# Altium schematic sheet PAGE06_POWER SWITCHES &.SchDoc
size 391 x 287 mm
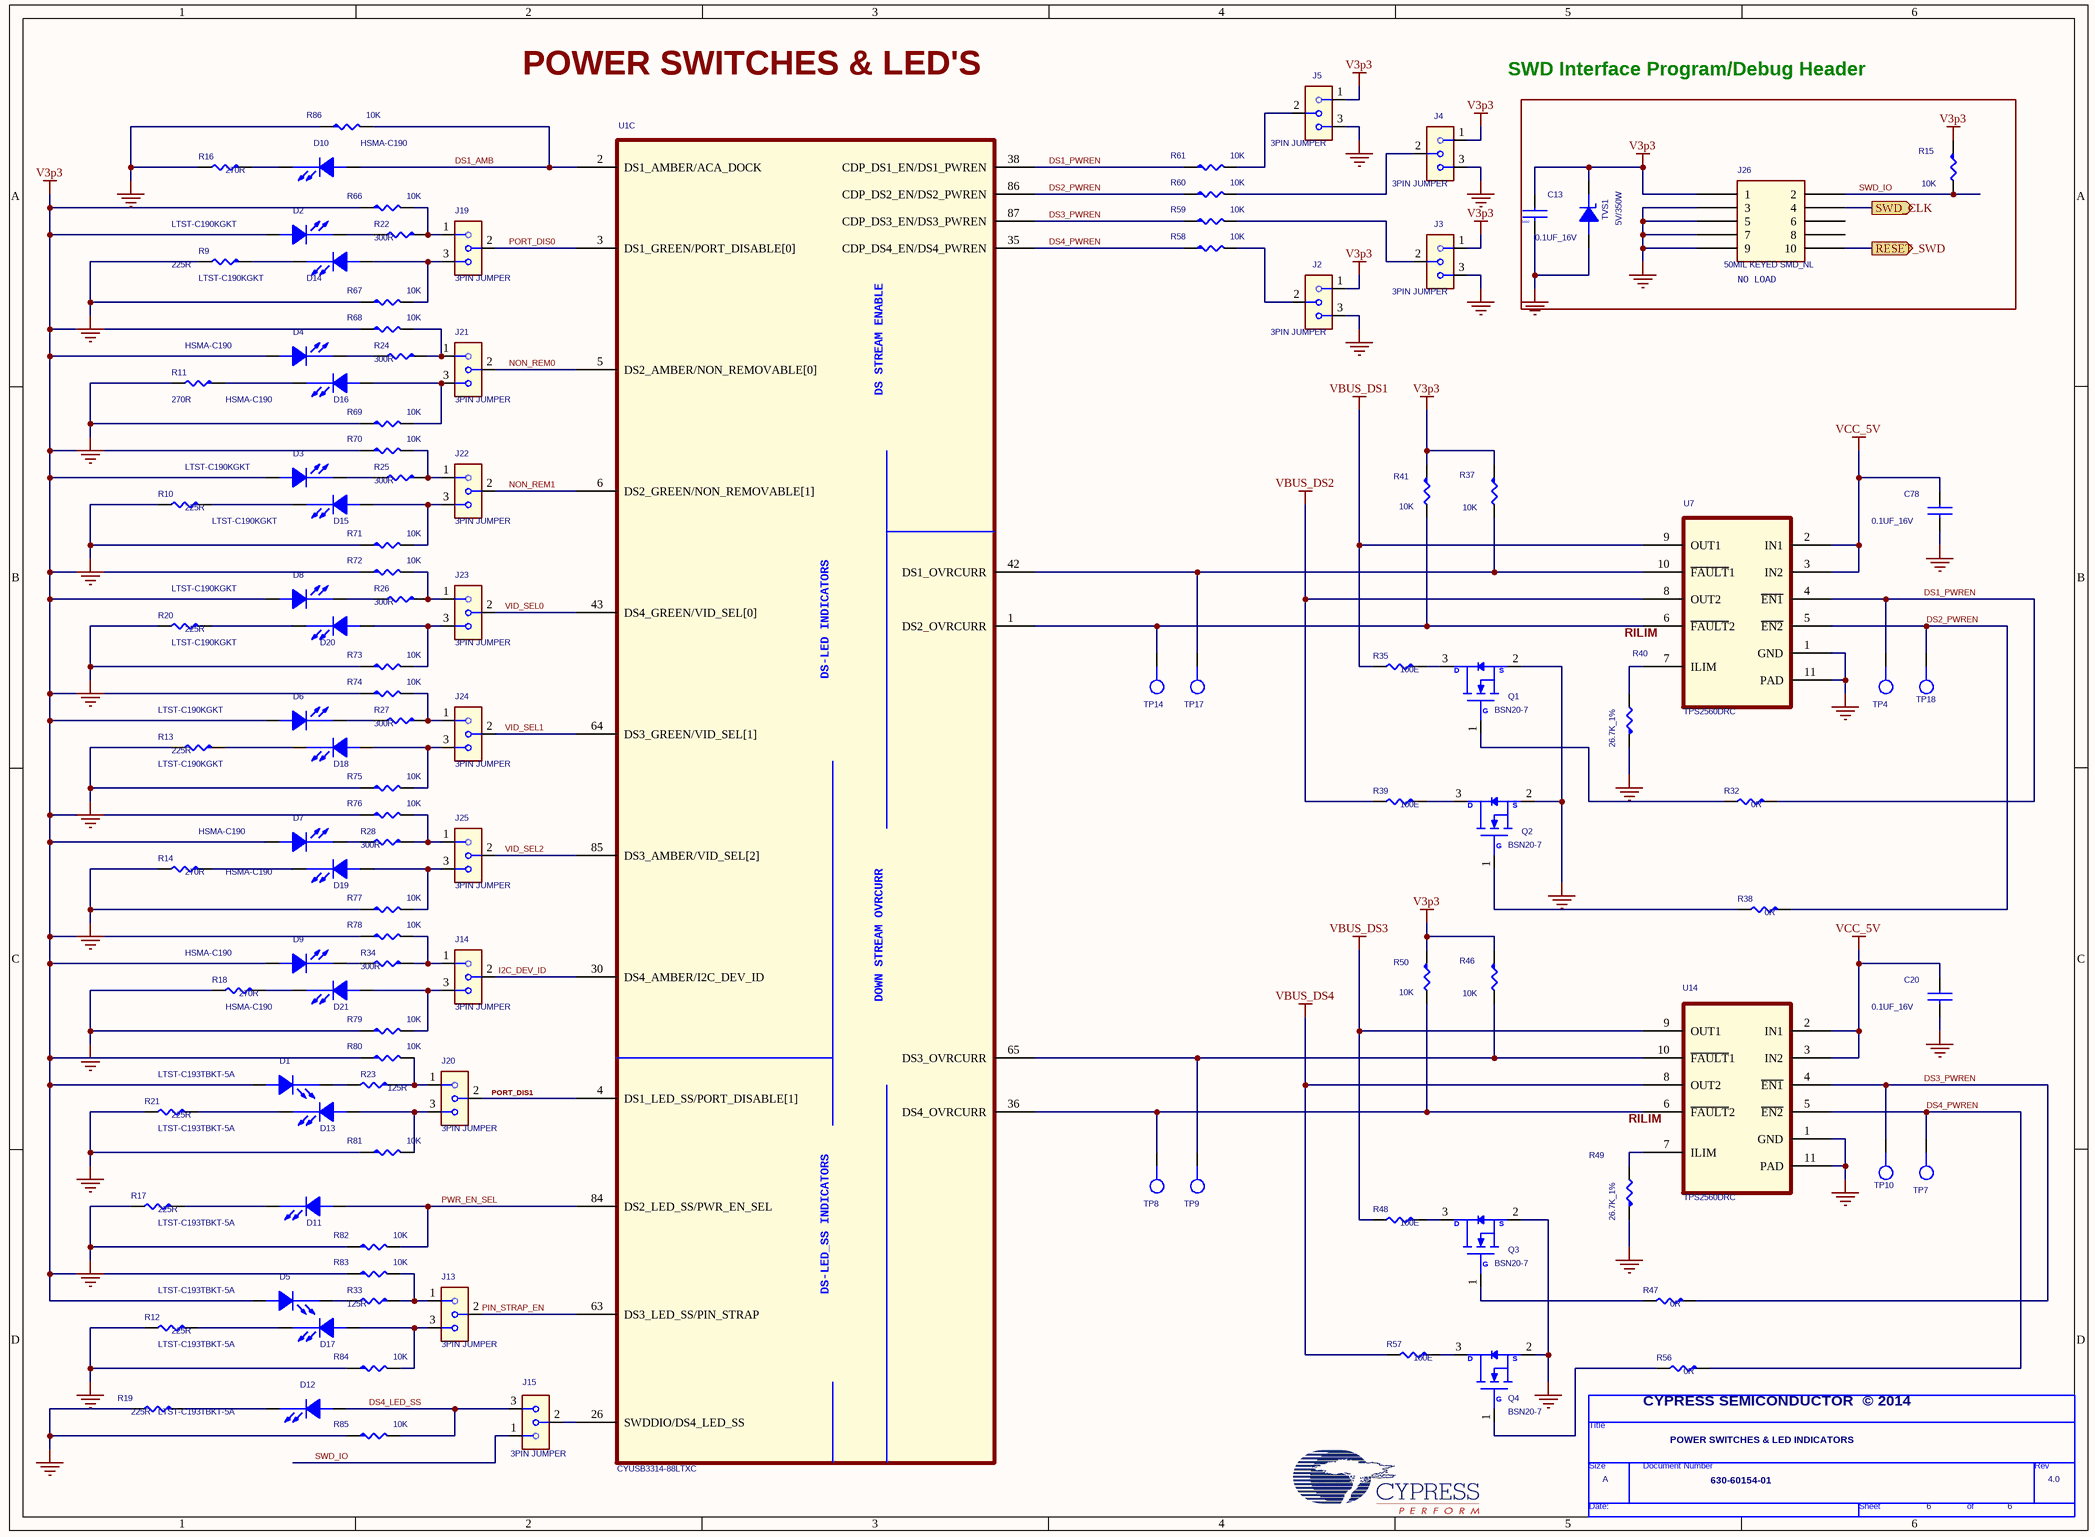
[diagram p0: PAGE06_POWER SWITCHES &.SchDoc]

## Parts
*  Page Count: 6  Page Size: A  Title: POWER SWITCHES & LED INDICATORS  RevCode: 4.0  Doc: 630-60154-01  (hidden comment: TitleBlock0)  (graphical)
C13  0.1UF_16V  [CAPC1005X55M]
C20  0.1UF_16V  [CAPC1005X56M]
C78  0.1UF_16V  [CAPC1005X56M]
D1  LTST-C193TBKT-5A  [LEDC1608X35M]
D2  LTST-C190KGKT  [LEDC1608X80M]
D3  LTST-C190KGKT  [LEDC1608X80M]
D4  HSMA-C190  [LEDC1608X80M]
D5  LTST-C193TBKT-5A  [LEDC1608X35M]
D6  LTST-C190KGKT  [LEDC1608X80M]
D7  HSMA-C190  [LEDC1608X80M]
D8  LTST-C190KGKT  [LEDC1608X80M]
D9  HSMA-C190  [LEDC1608X80M]
D10  HSMA-C190  [LEDC1608X80M]
D11  LTST-C193TBKT-5A  [LEDC1608X35M]
D12  LTST-C193TBKT-5A  [LEDC1608X35M]
D13  LTST-C193TBKT-5A  [LEDC1608X35M]
D14  LTST-C190KGKT  [LEDC1608X80M]
D15  LTST-C190KGKT  [LEDC1608X80M]
D16  HSMA-C190  [LEDC1608X80M]
D17  LTST-C193TBKT-5A  [LEDC1608X35M]
D18  LTST-C190KGKT  [LEDC1608X80M]
D19  HSMA-C190  [LEDC1608X80M]
D20  LTST-C190KGKT  [LEDC1608X80M]
D21  HSMA-C190  [LEDC1608X80M]
J2  3PIN JUMPER  [TE_3-644456-3]
J3  3PIN JUMPER  [TE_3-644456-3]
J4  3PIN JUMPER  [TE_3-644456-3]
J5  3PIN JUMPER  [TE_3-644456-3]
J13  3PIN JUMPER  [TE_3-644456-3]
J14  3PIN JUMPER  [TE_3-644456-3]
J15  3PIN JUMPER  [TE_3-644456-3]
J19  3PIN JUMPER  [TE_3-644456-3]
J20  3PIN JUMPER  [TE_3-644456-3]
J21  3PIN JUMPER  [TE_3-644456-3]
J22  3PIN JUMPER  [TE_3-644456-3]
J23  3PIN JUMPER  [TE_3-644456-3]
J24  3PIN JUMPER  [TE_3-644456-3]
J25  3PIN JUMPER  [TE_3-644456-3]
J26  50MIL KEYED SMD_NL  [SAMTEC_FTSH-105-01-L-DV-K]
Q1  BSN20-7  [SOT92P240X110-3M]
Q2  BSN20-7  [SOT92P240X110-3M]
Q3  BSN20-7  [SOT92P240X110-3M]
Q4  BSN20-7  [SOT92P240X110-3M]
R9  225R  [RESC1608X50M]
R10  225R  [RESC1608X50M]
R11  270R  [RESC1608X50M]
R12  225R  [RESC1608X50M]
R13  225R  [RESC1608X50M]
R14  270R  [RESC1608X50M]
R15  10K  [RESC1005X40M]
R16  270R  [RESC1608X50M]
R17  225R  [RESC1608X50M]
R18  270R  [RESC1608X50M]
R19  225R  [RESC1608X50M]
R20  225R  [RESC1608X50M]
R21  225R  [RESC1608X50M]
R22  300R  [RESC2012X65M]
R23  125R  [RESC2012X65M]
R24  300R  [RESC2012X65M]
R25  300R  [RESC2012X65M]
R26  300R  [RESC2012X65M]
R27  300R  [RESC2012X65M]
R28  300R  [RESC2012X65M]
R32  0R  [RESC1608X50M]
R33  125R  [RESC2012X65M]
R34  300R  [RESC2012X65M]
R35  100E  [RESC1608X50M]
R37  10K  [RESC1005X40M]
R38  0R  [RESC1608X50M]
R39  100E  [RESC1608X50M]
R40  26.7K_1%  [RESC1005X40M]
R41  10K  [RESC1005X40M]
R46  10K  [RESC1005X40M]
R47  0R  [RESC1608X50M]
R48  100E  [RESC1608X50M]
R49  26.7K_1%  [RESC1005X40M]
R50  10K  [RESC1005X40M]
R56  0R  [RESC1608X50M]
R57  100E  [RESC1608X50M]
R58  10K  [RESC1005X40M]
R59  10K  [RESC1005X40M]
R60  10K  [RESC1005X40M]
R61  10K  [RESC1005X40M]
R66  10K  [RESC1005X40M]
R67  10K  [RESC1005X40M]
R68  10K  [RESC1005X40M]
R69  10K  [RESC1005X40M]
R70  10K  [RESC1005X40M]
R71  10K  [RESC1005X40M]
R72  10K  [RESC1005X40M]
R73  10K  [RESC1005X40M]
R74  10K  [RESC1005X40M]
R75  10K  [RESC1005X40M]
R76  10K  [RESC1005X40M]
R77  10K  [RESC1005X40M]
R78  10K  [RESC1005X40M]
R79  10K  [RESC1005X40M]
R80  10K  [RESC1005X40M]
R81  10K  [RESC1005X40M]
R82  10K  [RESC1005X40M]
R83  10K  [RESC1005X40M]
R84  10K  [RESC1005X40M]
R85  10K  [RESC1005X40M]
R86  10K  [RESC1005X40M]
TP4  TEST POINT  [TP25C50]  (value not drawn)
TP7  TEST POINT  [TP25C50]  (value not drawn)
TP8  TEST POINT  [TP25C50]  (value not drawn)
TP9  TP_YEL  [KEYSTONE_5000]  (value not drawn)
TP10  TP_YEL  [KEYSTONE_5000]  (value not drawn)
TP14  TEST POINT  [TP25C50]  (value not drawn)
TP17  TP_YEL  [KEYSTONE_5000]  (value not drawn)
TP18  TP_YEL  [KEYSTONE_5000]  (value not drawn)
TVS1  5V/350W  [SOD2513X120M]
U1  CYUSB3314-88LTXC  [QFN40P1000X1000X100-89M]  (part C of 3)
U7  TPS2560DRC  [SON50P300X300X100-11M]
U14  TPS2560DRC  [SON50P300X300X100-11M]

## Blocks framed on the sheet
NO LOAD: C13 J26 R15 TVS1

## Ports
RESET_SWD (out), SWD_CLK (out)

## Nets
GND: C13.2 C20.2 C78.2 J2.3 J3.3 J4.3 J5.3 J26.3 J26.5 J26.7 J26.9 Q1.2(S) Q2.2(S) Q3.2(S) Q4.2(S) R9.2 R10.2 R11.2 R12.2 R13.2 R14.2 R16.2 R17.2 R18.2 R19.2 R20.2 R21.2 R40.1 R49.1 R67.1 R69.1 R71.1 R73.1 R75.1 R77.1 R79.1 R81.1 R82.1 R84.1 R85.1 R86.1 TVS1.2(A) U7.1(GND) U7.11(PAD) U14.1(GND) U14.11(PAD)
V3p3: C13.1 D1.1(ANODE) D2.1(ANODE) D3.1(ANODE) D4.1(ANODE) D5.1(ANODE) D6.1(ANODE) D7.1(ANODE) D8.1(ANODE) D9.1(ANODE) J2.1 J3.1 J4.1 J5.1 J26.1 R15.1 R37.1 R41.1 R46.1 R50.1 R66.1 R68.1 R70.1 R72.1 R74.1 R76.1 R78.1 R80.1 R83.1 TVS1.1(K)
VBUS_DS1: R35.2 U7.9(OUT1)
VBUS_DS2: R39.2 U7.8(OUT2)
VBUS_DS3: R48.2 U14.9(OUT1)
VBUS_DS4: R57.2 U14.8(OUT2)
VCC_5V: C20.1 C78.1 U7.2(IN1) U7.3(IN2) U14.2(IN1) U14.3(IN2)
DS1_AMB: D10.1(ANODE) R86.2 U1.2(DS1_AMBER/ACA_DOCK)
DS1_PWREN: R32.1 R61.1 TP4.1(TP) U1.38(CDP_DS1_EN/DS1_PWREN) U7.4(~{EN1})
DS2_PWREN: R38.1 R60.1 TP18.1(TP) U1.86(CDP_DS2_EN/DS2_PWREN) U7.5(~{EN2})
DS3_PWREN: R47.1 R59.1 TP10.1(TP) U1.87(CDP_DS3_EN/DS3_PWREN) U14.4(~{EN1})
DS4_LED_SS: D12.1(ANODE) J15.3 R85.2
DS4_PWREN: R56.1 R58.1 TP7.1(TP) U1.35(CDP_DS4_EN/DS4_PWREN) U14.5(~{EN2})
I2C_DEV_ID: J14.2 U1.30(DS4_AMBER/I2C_DEV_ID)
NON_REM0: J21.2 U1.5(DS2_AMBER/NON_REMOVABLE[0])
NON_REM1: J22.2 U1.6(DS2_GREEN/NON_REMOVABLE[1])
PIN_STRAP_EN: J13.2 U1.63(DS3_LED_SS/PIN_STRAP)
PORT_DIS0: J19.2 U1.3(DS1_GREEN/PORT_DISABLE[0])
PORT_DIS1: J20.2 U1.4(DS1_LED_SS/PORT_DISABLE[1])
PWR_EN_SEL: D11.1(ANODE) R82.2 U1.84(DS2_LED_SS/PWR_EN_SEL)
RESET_SWD: J26.10 ; port RESET_SWD
SWD_CLK: J26.4 ; port SWD_CLK
SWD_IO: J15.1 J26.2 R15.2
VID_SEL0: J23.2 U1.43(DS4_GREEN/VID_SEL[0])
VID_SEL1: J24.2 U1.64(DS3_GREEN/VID_SEL[1])
VID_SEL2: J25.2 U1.85(DS3_AMBER/VID_SEL[2])
NetD1_2: D1.2(CATHODE) R23.2
NetD2_2: D2.2(CATHODE) R22.2
NetD3_2: D3.2(CATHODE) R25.2
NetD4_2: D4.2(CATHODE) R24.2
NetD5_2: D5.2(CATHODE) R33.2
NetD6_2: D6.2(CATHODE) R27.2
NetD7_2: D7.2(CATHODE) R28.2
NetD8_2: D8.2(CATHODE) R26.2
NetD9_2: D9.2(CATHODE) R34.2
NetD10_2: D10.2(CATHODE) R16.1
NetD11_2: D11.2(CATHODE) R17.1
NetD12_2: D12.2(CATHODE) R19.1
NetD13_1: D13.1(ANODE) J20.3 R81.2
NetD13_2: D13.2(CATHODE) R21.1
NetD14_1: D14.1(ANODE) J19.3 R67.2
NetD14_2: D14.2(CATHODE) R9.1
NetD15_1: D15.1(ANODE) J22.3 R71.2
NetD15_2: D15.2(CATHODE) R10.1
NetD16_1: D16.1(ANODE) J21.3 R69.2
NetD16_2: D16.2(CATHODE) R11.1
NetD17_1: D17.1(ANODE) J13.3 R84.2
NetD17_2: D17.2(CATHODE) R12.1
NetD18_1: D18.1(ANODE) J24.3 R75.2
NetD18_2: D18.2(CATHODE) R13.1
NetD19_1: D19.1(ANODE) J25.3 R77.2
NetD19_2: D19.2(CATHODE) R14.1
NetD20_1: D20.1(ANODE) J23.3 R73.2
NetD20_2: D20.2(CATHODE) R20.1
NetD21_1: D21.1(ANODE) J14.3 R79.2
NetD21_2: D21.2(CATHODE) R18.1
NetJ2_2: J2.2 R58.2
NetJ3_2: J3.2 R59.2
NetJ4_2: J4.2 R60.2
NetJ5_2: J5.2 R61.2
NetJ13_1: J13.1 R33.1 R83.2
NetJ14_1: J14.1 R34.1 R78.2
NetJ15_2: J15.2 U1.26(SWDDIO/DS4_LED_SS)
NetJ19_1: J19.1 R22.1 R66.2
NetJ20_1: J20.1 R23.1 R80.2
NetJ21_1: J21.1 R24.1 R68.2
NetJ22_1: J22.1 R25.1 R70.2
NetJ23_1: J23.1 R26.1 R72.2
NetJ24_1: J24.1 R27.1 R74.2
NetJ25_1: J25.1 R28.1 R76.2
NetQ1_1: Q1.1(G) R32.2
NetQ1_3: Q1.3(D) R35.1
NetQ2_1: Q2.1(G) R38.2
NetQ2_3: Q2.3(D) R39.1
NetQ3_1: Q3.1(G) R47.2
NetQ3_3: Q3.3(D) R48.1
NetQ4_1: Q4.1(G) R56.2
NetQ4_3: Q4.3(D) R57.1
NetR37_2: R37.2 TP17.1(TP) U1.42(DS1_OVRCURR) U7.10(~{FAULT}1)
NetR40_2: R40.2 U7.7(ILIM)
NetR41_2: R41.2 TP14.1(TP) U1.1(DS2_OVRCURR) U7.6(~{FAULT}2)
NetR46_2: R46.2 TP9.1(TP) U1.65(DS3_OVRCURR) U14.10(~{FAULT}1)
NetR49_2: R49.2 U14.7(ILIM)
NetR50_2: R50.2 TP8.1(TP) U1.36(DS4_OVRCURR) U14.6(~{FAULT}2)

Not connected (* = marked no-connect by the designer): J26 6 8

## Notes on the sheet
- POWER SWITCHES & LED'S
- SWD Interface Program/Debug Header
- (near U7) RILIM
- (near U14) RILIM
- (near R56) CYPRESS SEMICONDUCTOR  © 2014

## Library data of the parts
C13 = 0.1 uFd 0402: CAP .1UF 16V CERAMIC Y5V 0402; Cy_part#: 730R-10010; Manufacturer: Panasonic - ECG; Part Number: ECJ-0EF1C104Z; DEVICE: 0p1uFd_0402; CLASS: DISCRETE; ALT_SYMBOLS: C-CC0402_A
C20 C78 = CAPACITOR NON-POL
D1-D21 = LED
J2 J4 J14 J23 J25 = 3PIN JUM: CONN HEADER VERT 3POS .100 TIN; Manufacturer: Tyco Electronics; Part Number: 3-644456-3
J3 J5 J13 J15 J19-J22 J24 = 3PIN JUM: CONN HEADER VERT 3POS .100 TIN; Part Number: 3-644456-3; Manufacturer: Tyco Electronics
J26 = 10 Pin Header 50mil Keyed SMD: CONN HEADER 10 PIN 50MIL KEYED SMD; Part Number: FTSH-105-01-L-DV-K; Manufacturer: Samtec; Cy_part#: 420R-14312; CLASS: IO; Last Edit By: SNF; DEVICE: HDR5x2x50KS
Q1-Q4 = BSN20-7: MOSFET N-CH 50V 500MA SOT23; Manufacturer: Diodes Inc; PSpiceTemplate: X^@REFDES %D %G %S @MODEL
R9-R14 R16-R28 R32-R35 R38 R39 R47 R48 R56 R57 = R_Dup1
R15 R37 R50 R58-R61 R66 R67 R70 R71 R73-R77 R79 R80 R82-R86 = R_Dup1: RES 10.0K OHM 1/10W 1% 0603 SMD; Manufacturer: Panasonic - ECG; Part Number: ERJ-3EKF1002V
R40 = R_Dup1: RES 28.0K OHM 1/10W 1% 0402 SMD; Manufacturer: Panasonic; Part Number: ERJ-2RKF2802X; Manufacturer Part Num: R5110402
R41 R46 R68 R69 R72 R78 R81 = R_Dup1: RES 10.0K OHM 1/10W 1% 0603 SMD; Part Number: ERJ-3EKF1002V; Manufacturer: Panasonic - ECG
R49 = R_Dup1: RES 28.0K OHM 1/10W 1% 0402 SMD; Part Number: ERJ-2RKF2802X; Manufacturer Part Num: R5110402; Manufacturer: Panasonic
TP4 TP7 TP8 TP14 = TP
TP9 TP17 = TP: TEST POINT PC MINI .040"D RED; Part Number: 5000; Manufacturer: Keystone
TP10 TP18 = TP: TEST POINT PC MINI .040"D RED; Manufacturer: Keystone; Part Number: 5000
TVS1 = TVS 5V SOD-323_0: TVS UNIDIR 350W 5V SOD-323; Part Number: SD05.TCT; Manufacturer: Dioded Inc.; CLASS: DISCRETE; DEVICE: SD05-7; LastEditBy: gir
U1 = CYUSB3314-88LTXC_2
